// TIA Portal project "SIKO_example_SN5oEPN_TIA_S71200" (V14)
// DEMO Project Adding SIKO SN5-Devices via ABC-EPN to S7-1200

(* hardware
DEVICE "S7-1200 station_1"  S7-1200 Station
   slot 0: "Rack_0"  S7-1200 Rack  Rack  V1.0
   slot 1: "PLC_1"  CPU 1215C DC/DC/DC  6ES7 215-1AG40-0XB0  V4.2
DEVICE "GSD device_1"  GSD.Device.PN
   slot 0: "Rack"  Rack  V1.0
   slot 0: "ABC-PRT"  RT Standard  AB7013-C  V3.03
      slot 0: "RT Standard"  RT Standard
      slot 1: "Interface"  Interface
         slot 1: "RJ45 100 MBit/s"  RJ45 100 MBit/s
   slot 1: "Input/Output 004 bytes_1"  Input/Output 004 bytes
      slot 0: "Input/Output 004 bytes"  Input/Output 004 bytes
   slot 2: "Input/Output 016 bytes_1"  Input/Output 016 bytes
      slot 0: "Input/Output 016 bytes"  Input/Output 016 bytes
   slot 3: "Input/Output 016 bytes_2"  Input/Output 016 bytes
      slot 0: "Input/Output 016 bytes"  Input/Output 016 bytes
*)

// ===== PLC "PLC_1"  CPU 1215C DC/DC/DC =====
// protected blocks, not shown: "SIKO_AG05_CSW_POS", "SIKO_POS_AP10vPN", "SIKO_SN5_COM", "SIKO_SN5_PRM"

ORGANIZATION_BLOCK "Main"   // OB1, SCL, ProgramCycle
TITLE = "Main Program Sweep (Cycle)"
{ S7_Optimized_Access := 'TRUE' }
VERSION : 0.1
   VAR_INPUT
      Initial_Call : Bool;   // Initial call of this OB
      Remanence : Bool;   // =True, if remanent data are available
   END_VAR
BEGIN
   // Siko device with node ID = 10
   "SIKO_POS_AP10vPN_DB310"(DC_StartByteOut:="ABC-PRT~Input_Output_016_bytes_1",
                            DC_StartByteIn:="ABC-PRT~Input_Output_016_bytes_1",
                            vnNodeId:=B#16#0A);
   // Siko device with node ID = 5
   "SIKO_SN5_COM_DB400"(DC_StartByte:="ABC-PRT~Input_Output_016_bytes_1_1",
                        nNodeId:=BYTE#16#05);
   "SIKO_AG05_CSW_POS_DB415"(DC_Com:="SIKO_SN5_COM_DB400");
   "SIKO_SN5_PRM_DB401"(DC_Com:="SIKO_SN5_COM_DB400");
END_ORGANIZATION_BLOCK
